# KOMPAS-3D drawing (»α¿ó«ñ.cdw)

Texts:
  ПЛК.303341.000 СБ
  Редуктор цилиндрический  двухступенчатый Сборочный чертеж
  Ревин ЕЕ
  Noncommercial version
  Лит-Масса-Масштаб
  Материал-Предприятие
  Технические требования :
  1. Смещение валов электродвигателя и редуктора
  не более :
  осевые           1 мм
  радиальные     0,3 мм
  угловое         1 30'
  2. Соединение вала электродвигателя и ведущего
  вала редуктора через муфту упругую втулочно-пальцевую
  ГОСТ 21424-75
  Технические требования
  Частота вращения ведущего вала редуктора n1=949 об/мин
  Крутящий момент на ведомом валу редуктора Т3=1429 Н*м
  Передаточное отношение быстроходной ступени i12=4,66
  Передаточное отношение тихоходной ступени i34=4.0
  Число зубев шестерни быстроходной ступени  z1=22
  Число зубьев колеса быстроходной ступени z2=101
  Число зубьев шестерни тихоходной ступени z3=22
  Число зубьев колеса тихоходной ступени z4=89
  Модуль зацепления быстроходной ступени mn12=2,0 мм
  Модуль зацепления тихоходной ступени mn34=2.5 мм
  Угол наклона зубьев быстроходной ступени  12 =29 16
  Symbol
  Угол наклона зубьев тихоходной ступени  34=29 53
  ACAD_ISO10W100_RGB_255_128_0_SC_1_THICK_0.15
  ACAD_ISO10W100_RGB_51_51_51_SC_1_THICK_0.15
  ACAD_ISO10W100_RGB_255_128_0_SC_0.5_THICK_0.15
  ACAD_ISO10W100_RGB_255_64_0_SC_1_THICK_0.15
  ACAD_ISO08W100_RGB_255_64_0_SC_1_THICK_0.15
  ACAD_ISO03W100_RGB_0_0_0_SC_0.3_THICK_0.15
  ACAD_ISO10W100_RGB_255_63_0_SC_1_THICK_0.15
  ACAD_ISO10W100_RGB_255_63_0_SC_0.25_THICK_0.15
  ACAD_ISO10W100_RGB_255_63_0_SC_0.5_THICK_0.15
  gost6_RGB_255_128_0_SC_1_THICK_0.15
  ACAD_ISO10W100_RGB_51_51_51_SC_1_THICK_0.18
  ACAD_ISO10W100_RGB_0_0_0_SC_1_THICK_0.18
  gost6_RGB_255_128_0_SC_0.5_THICK_0.15
  ACAD_ISO10W100_RGB_51_51_51_SC_0.1_THICK_0.25
  POLYLINE_STYLE_0.18_RGB_0_0_255
  ACAD_ISO10W100_RGB_255_128_0_SC_0.75_THICK_0.15
  ACAD_ISO03W100_RGB_0_0_255_SC_0.25_THICK_0.5
  ACAD_ISO03W100_RGB_0_0_0_SC_0.1_THICK_0.15
  ACAD_ISO10W100_RGB_255_128_0_SC_1_THICK_0.18
  ACAD_ISO10W100_RGB_51_51_51_SC_1_THICK_0.25
  ACAD_ISO10W100_RGB_0_0_255_SC_0.5_THICK_0.15
  СONTINUOUS_RGB_0_0_0_THICK_0.5
  ACAD_ISO10W100_RGB_255_128_0_SC_0.25_THICK_0.15
  ACAD_ISO10W100_RGB_255_64_0_SC_1_THICK_0.18
  Стили документа
  Подшипник 36207K ГОСТ 831-75
  Подшипник
  ГОСТ
  Подшипник 7212А ГОСТ 27365-87
  Подшипник207 ГОСТ 8338-75
  Подшипник209 ГОСТ 8338-75
  Манжета
  Шайба 8 Л БрКМц3-1 ГОСТ 6402-70
  Шайба пружинная
  Шайба
  БрКМц3-1
  БрКМц3-1 ГОСТ 18175-78
  Болт М8-6g x 22.109.30ХГСА ГОСТ 7808-70
  Болт
  .30ХГСА
  Сталь 30ХГСА ГОСТ 4543-71
  ANSI37
  Редуктор цилиндрический
  двухступенчатый
  Сборочный чертеж
  Вавилин В.В
  РЦО.112.00.00 СБ-
Dimensions and other numbers on the sheet: 50; 850; 950; 100; 106; 202; 112; 486; 105; 208; 478; 600; 2; 4; 6; 9; 11; 1; 3; 5; 7; 10; 12; 8; 13; 70; 55; 029; -6g; 1:1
